(* Logix 5000 project; controller DNP3Outstation 1756-L62 rev 19.11; software revision 19.01 *)

TASK MainTask (continuous, watchdog 500 ms) : DNP3Outstation

MODULES
   Local : 1756-L62 (ICP 0, rev 19.11)
      eth : vendor 1 type 12 code 200 (Ethernet 192.168.1.129, ICP 1, rev 5.7)
         DNPS01 : ETHERNET-MODULE (Ethernet 192.168.1.161, rev 1.1, Output RPI 10 ms)
END_MODULES

TYPE PLX51DNPInput :
STRUCT
   Instance : STRING;
   Status : PLX51DNPStatus;
   MasterMappedStatus : BOOL[1024];
   TransactionRate : DINT;
   Temperature : REAL;
   DNP3RxPacketCount : DINT;
   DNP3TxPacketCount : DINT;
   DNP3ChecksumErrors : DINT;
   DNP3MsgTimeout : DINT;
   AuthenticationFailures : DINT;
   SessionKeyChanges : DINT;
   TagReads : DINT;
   TagWrites : DINT;
   TagConnectionFailures : DINT;
   TagErrors : DINT;
   MasterEventBufferIndex : DINT;
END_STRUCT
END_TYPE

TYPE PLX51DNPOutput :
STRUCT
   RoutingInhibited : BOOL;
END_STRUCT
END_TYPE

TYPE PLX51DNPStatus :
STRUCT
   OutstationMode : BOOL;
   MasterMode : BOOL;
   UnscheduledMode : BOOL;
   ConfigurationValid : BOOL;
   RoutingInhibited : BOOL;
   DNP3EventLogOk : BOOL;
   DNP3EventLogOverflow : BOOL;
END_STRUCT
END_TYPE

TYPE PSDNP3AnalogInput16Flag :
STRUCT
   Online : BOOL;
   Restart : BOOL;
   CommLost : BOOL;
   RemoteForced : BOOL;
   LocalForced : BOOL;
   OverRange : BOOL;
   ReferenceError : BOOL;
   EventTrigger : BOOL;
   Value : INT;
END_STRUCT
END_TYPE

TYPE PSDNP3AnalogInput32Flag :
STRUCT
   Online : BOOL;
   Restart : BOOL;
   CommLost : BOOL;
   RemoteForced : BOOL;
   LocalForced : BOOL;
   OverRange : BOOL;
   ReferenceError : BOOL;
   EventTrigger : BOOL;
   Value : DINT;
END_STRUCT
END_TYPE

TYPE PSDNP3AnalogInputRealFlag :
STRUCT
   Online : BOOL;
   Restart : BOOL;
   CommLost : BOOL;
   RemoteForced : BOOL;
   LocalForced : BOOL;
   OverRange : BOOL;
   ReferenceError : BOOL;
   EventTrigger : BOOL;
   Value : REAL;
END_STRUCT
END_TYPE

TYPE PSDNP3AnalogOutput16 :
STRUCT
   RequestPending : BOOL;
   Reserved : INT;
   Value : INT;
   Status : SINT;
END_STRUCT
END_TYPE

TYPE PSDNP3AnalogOutput32 :
STRUCT
   RequestPending : BOOL;
   Reserved : INT;
   Value : DINT;
   Status : SINT;
END_STRUCT
END_TYPE

TYPE PSDNP3AnalogOutputReal :
STRUCT
   RequestPending : BOOL;
   Reserved : INT;
   Value : REAL;
   Status : SINT;
END_STRUCT
END_TYPE

TYPE PSDNP3AnalogOutputStatus16Flag :
STRUCT
   Online : BOOL;
   Restart : BOOL;
   CommLost : BOOL;
   RemoteForced : BOOL;
   LocalForced : BOOL;
   OverRange : BOOL;
   ReferenceError : BOOL;
   EventTrigger : BOOL;
   Value : INT;
END_STRUCT
END_TYPE

TYPE PSDNP3AnalogOutputStatus32Flag :
STRUCT
   Online : BOOL;
   Restart : BOOL;
   CommLost : BOOL;
   RemoteForced : BOOL;
   LocalForced : BOOL;
   OverRange : BOOL;
   ReferenceError : BOOL;
   EventTrigger : BOOL;
   Value : DINT;
END_STRUCT
END_TYPE

TYPE PSDNP3AnalogOutputStatusRealFlag :
STRUCT
   Online : BOOL;
   Restart : BOOL;
   CommLost : BOOL;
   RemoteForced : BOOL;
   LocalForced : BOOL;
   OverRange : BOOL;
   ReferenceError : BOOL;
   EventTrigger : BOOL;
   Value : REAL;
END_STRUCT
END_TYPE

TYPE PSDNP3BinaryInputPacked :
STRUCT
   BinaryValues : SINT[32];
END_STRUCT
END_TYPE

TYPE PSDNP3BinaryInputWithFlag :
STRUCT
   Online : BOOL;
   Restart : BOOL;
   CommLost : BOOL;
   RemoteForced : BOOL;
   LocalForced : BOOL;
   ChatterFilter : BOOL;
   Reserved : BOOL;
   State : BOOL;
END_STRUCT
END_TYPE

TYPE PSDNP3BinaryOutputPacked :
STRUCT
   BinaryValues : SINT[32];
END_STRUCT
END_TYPE

TYPE PSDNP3BinaryOutputPulse :
STRUCT
   Count : SINT;
   OnTimer : TIMER;
   OffTimer : TIMER;
END_STRUCT
END_TYPE

TYPE PSDNP3BinaryOutputWithFlag :
STRUCT
   Online : BOOL;
   Restart : BOOL;
   CommLost : BOOL;
   RemoteForced : BOOL;
   LocalForced : BOOL;
   Reserved1 : BOOL;
   Reserved2 : BOOL;
   State : BOOL;
END_STRUCT
END_TYPE

TYPE PSDNP3Counter16WithFlag :
STRUCT
   Online : BOOL;
   Restart : BOOL;
   CommLost : BOOL;
   RemoteForced : BOOL;
   LocalForced : BOOL;
   RollOver : BOOL;
   Discontinuity : BOOL;
   EventTrigger : BOOL;
   Value : INT;
END_STRUCT
END_TYPE

TYPE PSDNP3Counter32WithFlag :
STRUCT
   Online : BOOL;
   Restart : BOOL;
   CommLost : BOOL;
   RemoteForced : BOOL;
   LocalForced : BOOL;
   RollOver : BOOL;
   Discontinuity : BOOL;
   EventTrigger : BOOL;
   Value : DINT;
END_STRUCT
END_TYPE

TYPE PSDNP3CounterCtrl :
STRUCT
   FreezeCounter : BOOL;
   ClearCounter : BOOL;
   TimeOfOccurrence : LINT;
END_STRUCT
END_TYPE

TYPE PSDNP3CROB :
STRUCT
   RequestPending : BOOL;
   Reserved : INT;
   ControlCode : SINT;
   Count : SINT;
   OnTime : DINT;
   OffTime : DINT;
   StatusCode : SINT;
END_STRUCT
END_TYPE

TYPE PSDNP3DoubleBinaryInputPacked :
STRUCT
   BinaryValues : SINT[32];
END_STRUCT
END_TYPE

TYPE PSDNP3DoubleBinaryInputWithFlag :
STRUCT
   Online : BOOL;
   Restart : BOOL;
   CommLost : BOOL;
   RemoteForced : BOOL;
   LocalForced : BOOL;
   ChatterFilter : BOOL;
   State0 : BOOL;
   State1 : BOOL;
END_STRUCT
END_TYPE

TYPE PSDNP3FrozenCounter16WithFlag :
STRUCT
   Online : BOOL;
   Restart : BOOL;
   CommLost : BOOL;
   RemoteForced : BOOL;
   LocalForced : BOOL;
   RollOver : BOOL;
   Discontinuity : BOOL;
   EventTrigger : BOOL;
   Value : INT;
END_STRUCT
END_TYPE

TYPE PSDNP3FrozenCounter16WithFlagTimeRev2 :
STRUCT
   Online : BOOL;
   Restart : BOOL;
   CommLost : BOOL;
   RemoteForced : BOOL;
   LocalForced : BOOL;
   RollOver : BOOL;
   Discontinuity : BOOL;
   EventTrigger : BOOL;
   Value : INT;
   Reserved : DINT;
   TimeOfOccurrence : LINT;
END_STRUCT
END_TYPE

TYPE PSDNP3FrozenCounter32WithFlag :
STRUCT
   Online : BOOL;
   Restart : BOOL;
   CommLost : BOOL;
   RemoteForced : BOOL;
   LocalForced : BOOL;
   RollOver : BOOL;
   Discontinuity : BOOL;
   EventTrigger : BOOL;
   Value : DINT;
END_STRUCT
END_TYPE

TYPE PSDNP3FrozenCounter32WithFlagTime :
STRUCT
   Online : BOOL;
   Restart : BOOL;
   CommLost : BOOL;
   RemoteForced : BOOL;
   LocalForced : BOOL;
   RollOver : BOOL;
   Discontinuity : BOOL;
   EventTrigger : BOOL;
   Value : DINT;
   TimeOfOccurrence : LINT;
END_STRUCT
END_TYPE

TYPE PSDNP3LocalKeyUpdateRequest :
STRUCT
   KeyLength : SINT;
   KeyData : SINT[32];
END_STRUCT
END_TYPE

TYPE PSDNP3MasterEvent :
STRUCT
   EvtPending : DINT;
   EvtGroup : SINT;
   EvtFlags : SINT;
   EvtSrcNodeAddress : INT;
   EvtSrcIPAddress : INT[4];
   EvtElementIndex : DINT;
   Reserved : DINT;
   EvtTimeStamp : LINT;
   EvtFloatValue : REAL;
   EvtIntegerValue : DINT;
END_STRUCT
END_TYPE

TYPE PSDNP3RemoteKeyUpdateRequest :
STRUCT
   Command : SINT;
   Option : SINT;
   DestinationNode : INT;
   IPAddress : INT[4];
   KeyData : SINT[255];
END_STRUCT
END_TYPE

ADD_ON_INSTRUCTION PSDNP3AnalogInputEvtLog16   (* revision 1.0, vendor ProSoft Technology Inc *)
VAR_IN_OUT
   DNP3Object : PSDNP3AnalogInput16Flag; {required}
END_VAR
VAR_INPUT
   Deadband : INT; {required}
   MinimumLogInterval : REAL; {required}
   ExtrernalEventTrigger : BOOL; {visible}
END_VAR
VAR_OUTPUT
   EventTriggers : DINT; {access Read Only, visible}
END_VAR
VAR
   RequestLog : BOOL; {access None}
   ExternalONS : BOOL; {access None}
   Interval : TIMER := (PRE := 1000000); {access None}
   PreviousValue : INT; {access None}
   DBRequest : BOOL; {access None}
   ExtRequest : BOOL; {access None}
   Pending : BOOL; {access None}
END_VAR

ROUTINE Logic   (* ladder *)
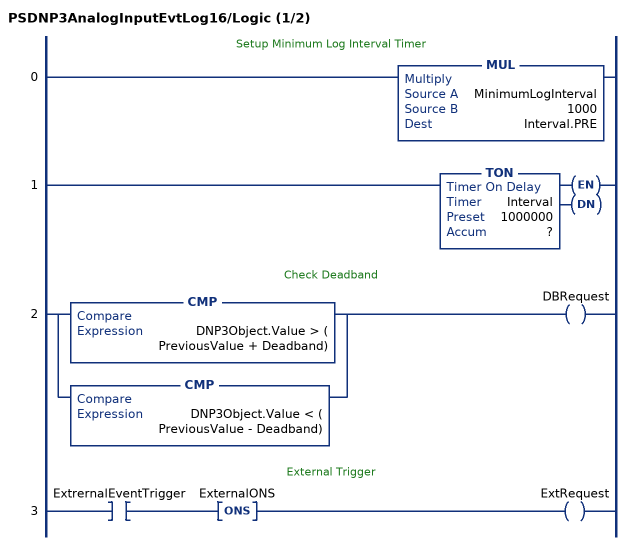
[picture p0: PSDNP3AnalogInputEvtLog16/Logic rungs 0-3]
   // Setup Minimum Log Interval Timer
   0: MUL(MinimumLogInterval,1000,Interval.PRE);
   1: TON(Interval,?,?);
   // Check Deadband
   2: [CMP(DNP3Object.Value > ( PreviousValue + Deadband)) ,CMP(DNP3Object.Value < ( PreviousValue - Deadband)) ]OTE(DBRequest);
   // External Trigger
   3: XIC(ExtrernalEventTrigger)ONS(ExternalONS)OTE(ExtRequest);
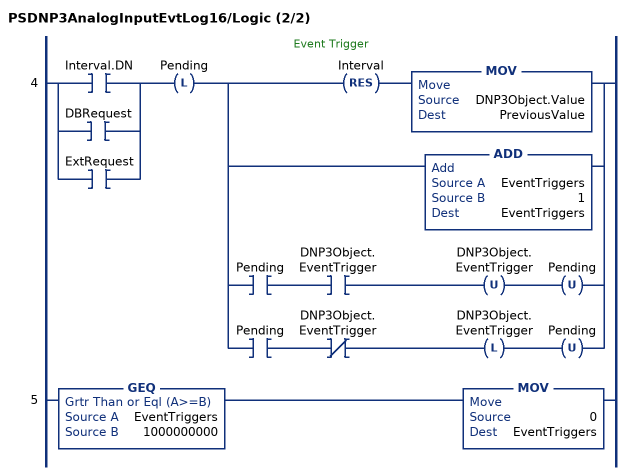
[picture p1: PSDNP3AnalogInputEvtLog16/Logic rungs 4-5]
   // Event Trigger
   4: [XIC(Interval.DN) ,XIC(DBRequest) ,XIC(ExtRequest) ]OTL(Pending)[RES(Interval) MOV(DNP3Object.Value,PreviousValue) ,ADD(EventTriggers,1,EventTriggers) ,XIC(Pending) XIC(DNP3Object.EventTrigger) OTU(DNP3Object.EventTrigger) OTU(Pending) ,XIC(Pending) XIO(DNP3Object.EventTrigger) OTL(DNP3Object.EventTrigger) OTU(Pending) ];
   5: GEQ(EventTriggers,1000000000)MOV(0,EventTriggers);
END_ROUTINE
END_ADD_ON_INSTRUCTION

ADD_ON_INSTRUCTION PSDNP3AnalogInputEvtLog32   (* revision 1.0, vendor ProSoft Technology Inc *)
VAR_IN_OUT
   DNP3Object : PSDNP3AnalogInput32Flag; {required}
END_VAR
VAR_INPUT
   Deadband : DINT; {required}
   MinimumLogInterval : REAL; {required}
   ExtrernalEventTrigger : BOOL; {visible}
END_VAR
VAR_OUTPUT
   EventTriggers : DINT; {access Read Only, visible}
END_VAR
VAR
   RequestLog : BOOL; {access None}
   ExternalONS : BOOL; {access None}
   Interval : TIMER := (PRE := 1000000); {access None}
   PreviousValue : DINT; {access None}
   DBRequest : BOOL; {access None}
   ExtRequest : BOOL; {access None}
   Pending : BOOL; {access None}
END_VAR

ROUTINE Logic   (* ladder *)
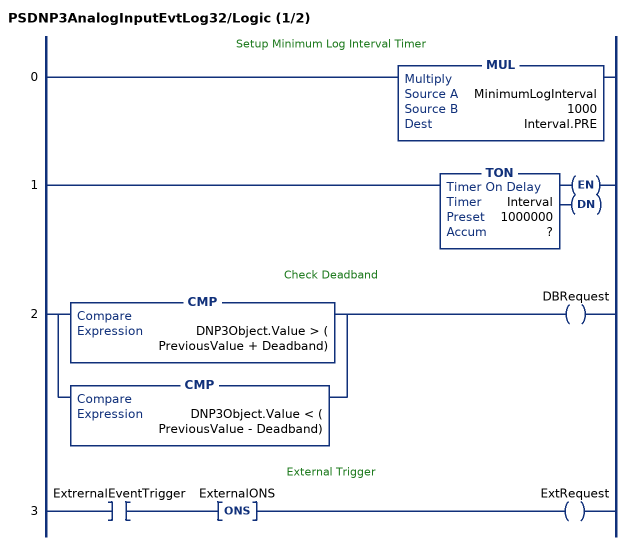
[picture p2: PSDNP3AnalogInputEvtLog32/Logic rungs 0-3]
   // Setup Minimum Log Interval Timer
   0: MUL(MinimumLogInterval,1000,Interval.PRE);
   1: TON(Interval,?,?);
   // Check Deadband
   2: [CMP(DNP3Object.Value > ( PreviousValue + Deadband)) ,CMP(DNP3Object.Value < ( PreviousValue - Deadband)) ]OTE(DBRequest);
   // External Trigger
   3: XIC(ExtrernalEventTrigger)ONS(ExternalONS)OTE(ExtRequest);
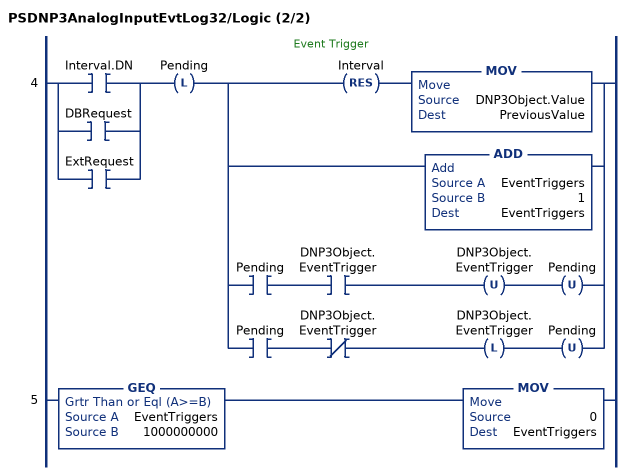
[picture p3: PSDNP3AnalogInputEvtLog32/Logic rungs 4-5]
   // Event Trigger
   4: [XIC(Interval.DN) ,XIC(DBRequest) ,XIC(ExtRequest) ]OTL(Pending)[RES(Interval) MOV(DNP3Object.Value,PreviousValue) ,ADD(EventTriggers,1,EventTriggers) ,XIC(Pending) XIC(DNP3Object.EventTrigger) OTU(DNP3Object.EventTrigger) OTU(Pending) ,XIC(Pending) XIO(DNP3Object.EventTrigger) OTL(DNP3Object.EventTrigger) OTU(Pending) ];
   5: GEQ(EventTriggers,1000000000)MOV(0,EventTriggers);
END_ROUTINE
END_ADD_ON_INSTRUCTION

ADD_ON_INSTRUCTION PSDNP3AnalogInputEvtLogReal   (* revision 1.0, vendor ProSoft Technology Inc *)
VAR_IN_OUT
   DNP3Object : PSDNP3AnalogInputRealFlag; {required}
END_VAR
VAR_INPUT
   Deadband : REAL; {required}
   MinimumLogInterval : REAL; {required}
   ExtrernalEventTrigger : BOOL; {visible}
END_VAR
VAR_OUTPUT
   EventTriggers : DINT; {access Read Only, visible}
END_VAR
VAR
   RequestLog : BOOL; {access None}
   ExternalONS : BOOL; {access None}
   Interval : TIMER := (PRE := 1000000); {access None}
   PreviousValue : REAL; {access None}
   DBRequest : BOOL; {access None}
   ExtRequest : BOOL; {access None}
   Pending : BOOL; {access None}
END_VAR

ROUTINE Logic   (* ladder *)
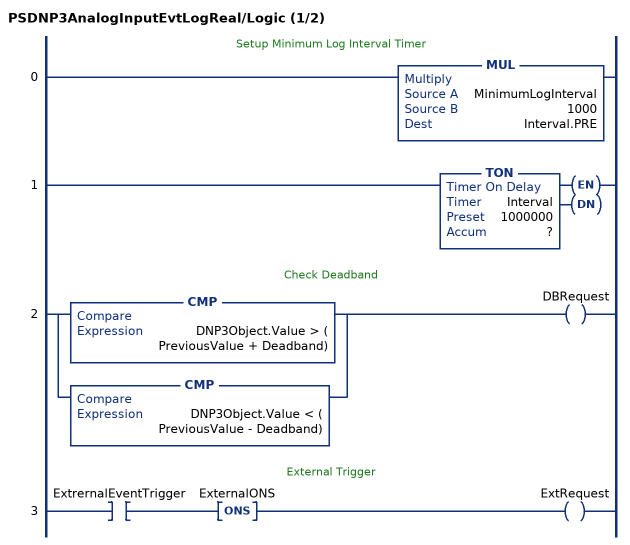
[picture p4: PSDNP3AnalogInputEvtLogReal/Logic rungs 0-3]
   // Setup Minimum Log Interval Timer
   0: MUL(MinimumLogInterval,1000,Interval.PRE);
   1: TON(Interval,?,?);
   // Check Deadband
   2: [CMP(DNP3Object.Value > ( PreviousValue + Deadband)) ,CMP(DNP3Object.Value < ( PreviousValue - Deadband)) ]OTE(DBRequest);
   // External Trigger
   3: XIC(ExtrernalEventTrigger)ONS(ExternalONS)OTE(ExtRequest);
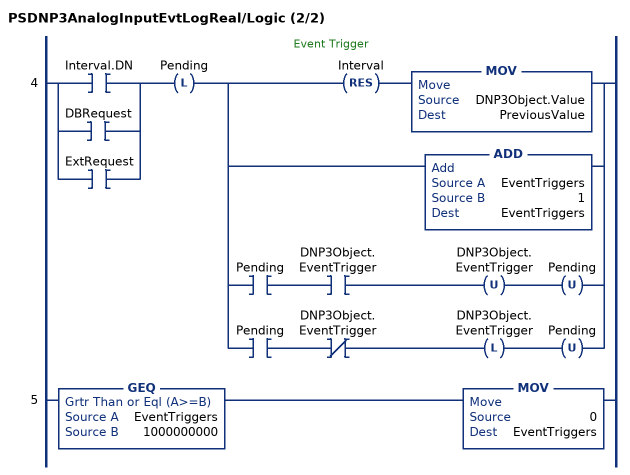
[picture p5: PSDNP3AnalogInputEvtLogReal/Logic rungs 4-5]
   // Event Trigger
   4: [XIC(Interval.DN) ,XIC(DBRequest) ,XIC(ExtRequest) ]OTL(Pending)[RES(Interval) MOV(DNP3Object.Value,PreviousValue) ,ADD(EventTriggers,1,EventTriggers) ,XIC(Pending) XIC(DNP3Object.EventTrigger) OTU(DNP3Object.EventTrigger) OTU(Pending) ,XIC(Pending) XIO(DNP3Object.EventTrigger) OTL(DNP3Object.EventTrigger) OTU(Pending) ];
   5: GEQ(EventTriggers,1000000000)MOV(0,EventTriggers);
END_ROUTINE
END_ADD_ON_INSTRUCTION

ADD_ON_INSTRUCTION PSDNP3AnalogOutput16Control   (* revision 1.0, vendor ProSoft Technology Inc *)
// DNP3 Outstation - Analog Output Control 16
VAR_IN_OUT
   AnalogOutputCommand : PSDNP3AnalogOutput16; {required}
   AnalogOutputStatus : PSDNP3AnalogOutputStatus16Flag; {required}
END_VAR
VAR_OUTPUT
   CurrentOutput : INT; {access Read Only, visible}
   RequestCount : DINT; {access Read Only, visible}
END_VAR
VAR_INPUT
   ResetStatistics : BOOL; {required}
END_VAR
VAR
   RequestCounter : COUNTER := (PRE := 2100000000); {access None}
END_VAR

ROUTINE Logic   (* ladder *)
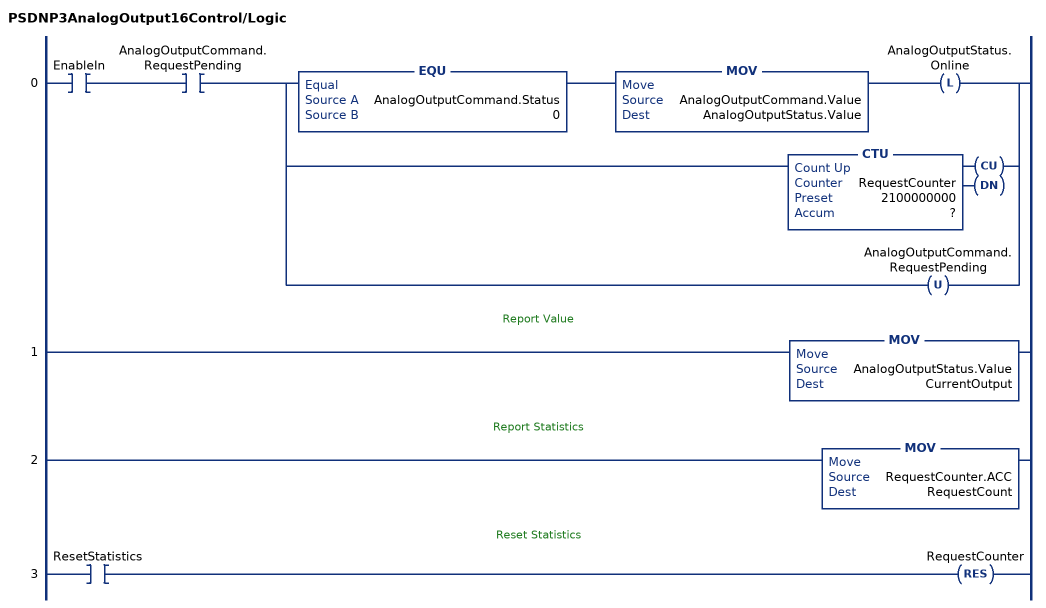
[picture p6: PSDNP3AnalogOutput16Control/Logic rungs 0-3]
   0: XIC(EnableIn)XIC(AnalogOutputCommand.RequestPending)[EQU(AnalogOutputCommand.Status,0) MOV(AnalogOutputCommand.Value,AnalogOutputStatus.Value) OTL(AnalogOutputStatus.Online) ,CTU(RequestCounter,?,?) ,OTU(AnalogOutputCommand.RequestPending) ];
   // Report Value
   1: MOV(AnalogOutputStatus.Value,CurrentOutput);
   // Report Statistics
   2: MOV(RequestCounter.ACC,RequestCount);
   // Reset Statistics
   3: XIC(ResetStatistics)RES(RequestCounter);
END_ROUTINE
END_ADD_ON_INSTRUCTION

ADD_ON_INSTRUCTION PSDNP3AnalogOutput32Control   (* revision 1.0, vendor ProSoft Technology Inc *)
// DNP3 Outstation - Analog Output Control REAL
VAR_IN_OUT
   AnalogOutputCommand : PSDNP3AnalogOutput32; {required}
   AnalogOutputStatus : PSDNP3AnalogOutputStatus32Flag; {required}
END_VAR
VAR_OUTPUT
   CurrentOutput : DINT; {access Read Only, visible}
   RequestCount : DINT; {access Read Only, visible}
END_VAR
VAR_INPUT
   ResetStatistics : BOOL; {required}
END_VAR
VAR
   RequestCounter : COUNTER := (PRE := 2100000000); {access None}
END_VAR

ROUTINE Logic   (* ladder *)
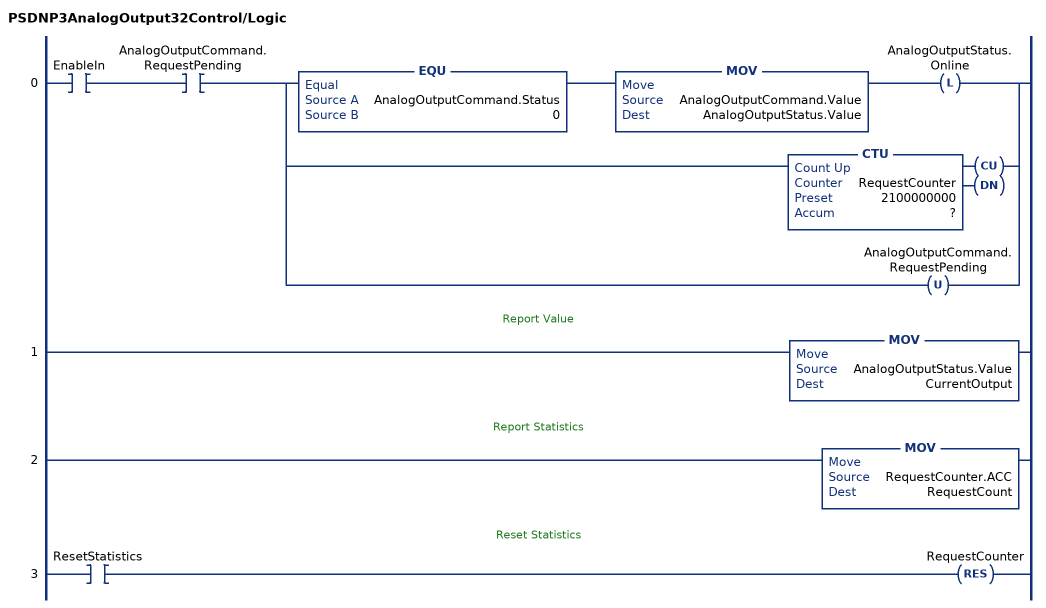
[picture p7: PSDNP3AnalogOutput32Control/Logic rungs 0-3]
   0: XIC(EnableIn)XIC(AnalogOutputCommand.RequestPending)[EQU(AnalogOutputCommand.Status,0) MOV(AnalogOutputCommand.Value,AnalogOutputStatus.Value) OTL(AnalogOutputStatus.Online) ,CTU(RequestCounter,?,?) ,OTU(AnalogOutputCommand.RequestPending) ];
   // Report Value
   1: MOV(AnalogOutputStatus.Value,CurrentOutput);
   // Report Statistics
   2: MOV(RequestCounter.ACC,RequestCount);
   // Reset Statistics
   3: XIC(ResetStatistics)RES(RequestCounter);
END_ROUTINE
END_ADD_ON_INSTRUCTION

ADD_ON_INSTRUCTION PSDNP3AnalogOutputRealControl   (* revision 1.0, vendor ProSoft Technology Inc *)
// DNP3 Outstation - Analog Output Control REAL
VAR_IN_OUT
   AnalogOutputCommand : PSDNP3AnalogOutputReal; {required}
   AnalogOutputStatus : PSDNP3AnalogOutputStatusRealFlag; {required}
END_VAR
VAR_OUTPUT
   CurrentOutput : REAL; {access Read Only, visible}
   RequestCount : DINT; {access Read Only, visible}
END_VAR
VAR_INPUT
   ResetStatistics : BOOL; {required}
END_VAR
VAR
   RequestCounter : COUNTER := (PRE := 2100000000); {access None}
END_VAR

ROUTINE Logic   (* ladder *)
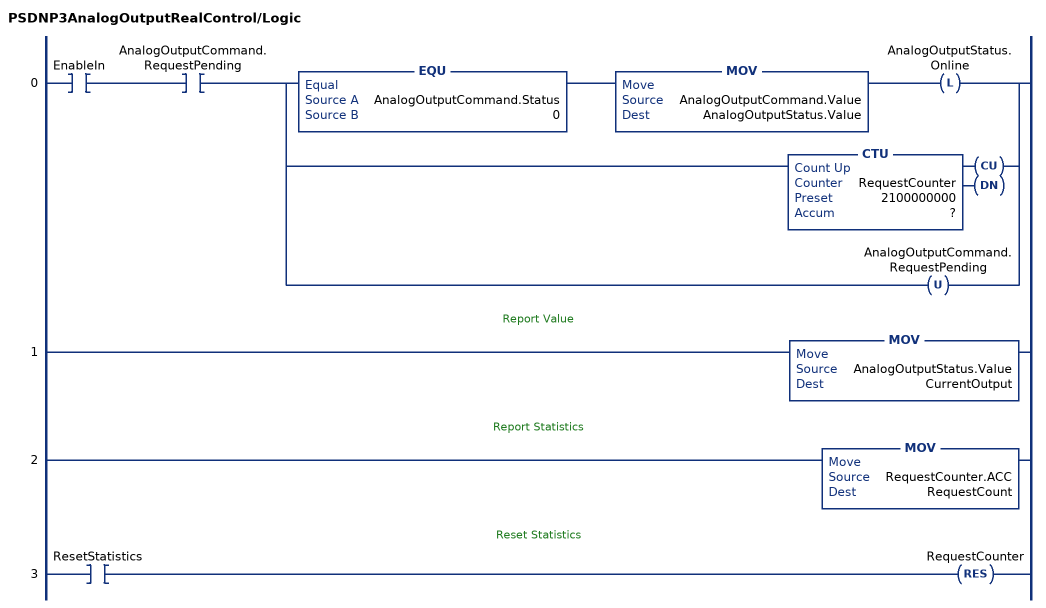
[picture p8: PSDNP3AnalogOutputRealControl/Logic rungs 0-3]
   0: XIC(EnableIn)XIC(AnalogOutputCommand.RequestPending)[EQU(AnalogOutputCommand.Status,0) MOV(AnalogOutputCommand.Value,AnalogOutputStatus.Value) OTL(AnalogOutputStatus.Online) ,CTU(RequestCounter,?,?) ,OTU(AnalogOutputCommand.RequestPending) ];
   // Report Value
   1: MOV(AnalogOutputStatus.Value,CurrentOutput);
   // Report Statistics
   2: MOV(RequestCounter.ACC,RequestCount);
   // Reset Statistics
   3: XIC(ResetStatistics)RES(RequestCounter);
END_ROUTINE
END_ADD_ON_INSTRUCTION

ADD_ON_INSTRUCTION PSDNP3AnalogOutputStatusEvtLog16   (* revision 1.0, vendor ProSoft Technology Inc *)
VAR_IN_OUT
   DNP3Object : PSDNP3AnalogOutputStatus32Flag; {required}
END_VAR
VAR_INPUT
   Deadband : INT; {required}
   MinimumLogInterval : REAL; {required}
   ExtrernalEventTrigger : BOOL; {visible}
END_VAR
VAR_OUTPUT
   EventTriggers : DINT; {access Read Only, visible}
END_VAR
VAR
   RequestLog : BOOL; {access None}
   ExternalONS : BOOL; {access None}
   Interval : TIMER := (PRE := 1000000); {access None}
   PreviousValue : INT; {access None}
   DBRequest : BOOL; {access None}
   ExtRequest : BOOL; {access None}
   Pending : BOOL; {access None}
END_VAR

ROUTINE Logic   (* ladder *)
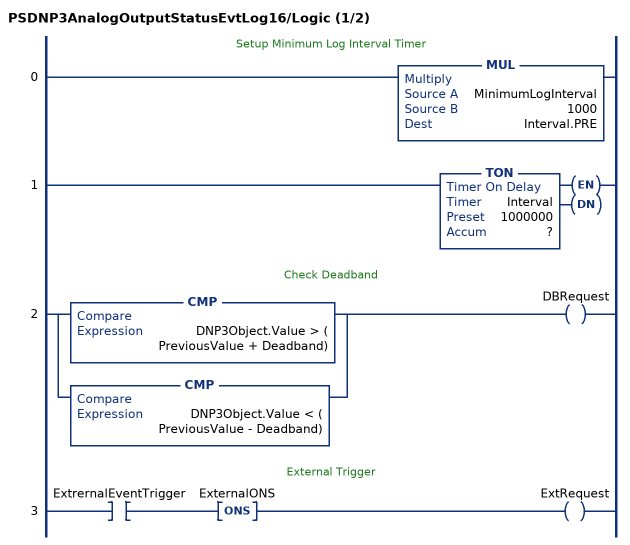
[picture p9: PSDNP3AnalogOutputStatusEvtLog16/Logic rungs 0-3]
   // Setup Minimum Log Interval Timer
   0: MUL(MinimumLogInterval,1000,Interval.PRE);
   1: TON(Interval,?,?);
   // Check Deadband
   2: [CMP(DNP3Object.Value > ( PreviousValue + Deadband)) ,CMP(DNP3Object.Value < ( PreviousValue - Deadband)) ]OTE(DBRequest);
   // External Trigger
   3: XIC(ExtrernalEventTrigger)ONS(ExternalONS)OTE(ExtRequest);
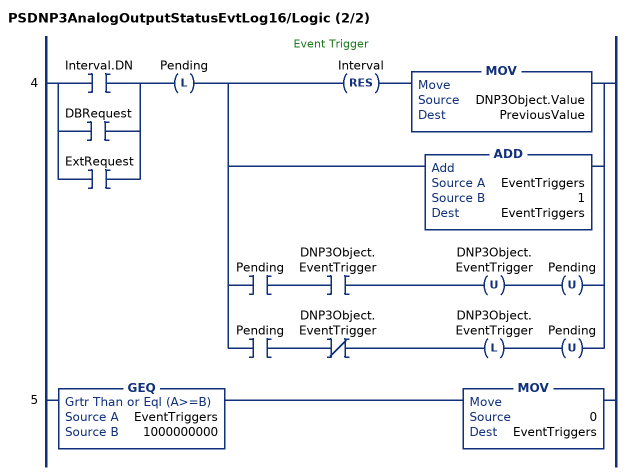
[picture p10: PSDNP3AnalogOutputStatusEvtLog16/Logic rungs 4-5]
   // Event Trigger
   4: [XIC(Interval.DN) ,XIC(DBRequest) ,XIC(ExtRequest) ]OTL(Pending)[RES(Interval) MOV(DNP3Object.Value,PreviousValue) ,ADD(EventTriggers,1,EventTriggers) ,XIC(Pending) XIC(DNP3Object.EventTrigger) OTU(DNP3Object.EventTrigger) OTU(Pending) ,XIC(Pending) XIO(DNP3Object.EventTrigger) OTL(DNP3Object.EventTrigger) OTU(Pending) ];
   5: GEQ(EventTriggers,1000000000)MOV(0,EventTriggers);
END_ROUTINE
END_ADD_ON_INSTRUCTION

ADD_ON_INSTRUCTION PSDNP3AnalogOutputStatusEvtLog32   (* revision 1.0, vendor ProSoft Technology Inc *)
VAR_IN_OUT
   DNP3Object : PSDNP3AnalogOutputStatus32Flag; {required}
END_VAR
VAR_INPUT
   Deadband : DINT; {required}
   MinimumLogInterval : REAL; {required}
   ExtrernalEventTrigger : BOOL; {visible}
END_VAR
VAR_OUTPUT
   EventTriggers : DINT; {access Read Only, visible}
END_VAR
VAR
   RequestLog : BOOL; {access None}
   ExternalONS : BOOL; {access None}
   Interval : TIMER := (PRE := 1000000); {access None}
   PreviousValue : DINT; {access None}
   DBRequest : BOOL; {access None}
   ExtRequest : BOOL; {access None}
   Pending : BOOL; {access None}
END_VAR

ROUTINE Logic   (* ladder *)
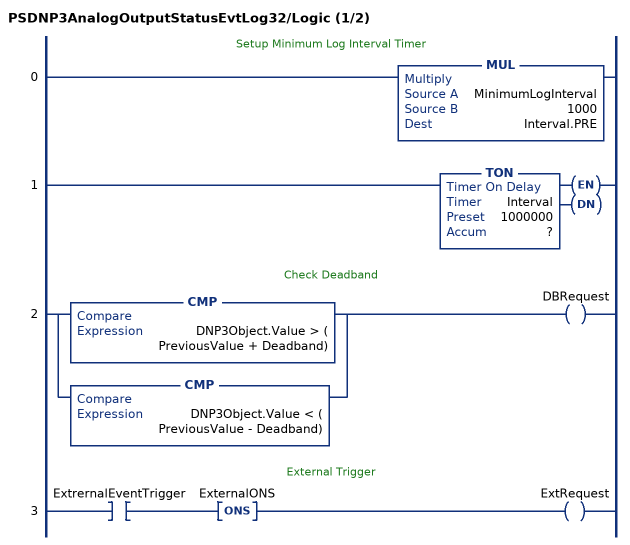
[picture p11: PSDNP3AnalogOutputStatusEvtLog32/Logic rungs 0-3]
   // Setup Minimum Log Interval Timer
   0: MUL(MinimumLogInterval,1000,Interval.PRE);
   1: TON(Interval,?,?);
   // Check Deadband
   2: [CMP(DNP3Object.Value > ( PreviousValue + Deadband)) ,CMP(DNP3Object.Value < ( PreviousValue - Deadband)) ]OTE(DBRequest);
   // External Trigger
   3: XIC(ExtrernalEventTrigger)ONS(ExternalONS)OTE(ExtRequest);
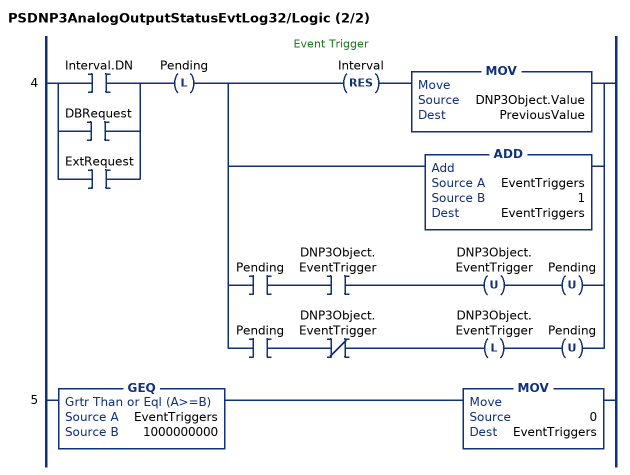
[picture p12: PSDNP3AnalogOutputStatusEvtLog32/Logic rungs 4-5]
   // Event Trigger
   4: [XIC(Interval.DN) ,XIC(DBRequest) ,XIC(ExtRequest) ]OTL(Pending)[RES(Interval) MOV(DNP3Object.Value,PreviousValue) ,ADD(EventTriggers,1,EventTriggers) ,XIC(Pending) XIC(DNP3Object.EventTrigger) OTU(DNP3Object.EventTrigger) OTU(Pending) ,XIC(Pending) XIO(DNP3Object.EventTrigger) OTL(DNP3Object.EventTrigger) OTU(Pending) ];
   5: GEQ(EventTriggers,1000000000)MOV(0,EventTriggers);
END_ROUTINE
END_ADD_ON_INSTRUCTION

ADD_ON_INSTRUCTION PSDNP3AnalogOutputStatusEvtLogReal   (* revision 1.0, vendor ProSoft Technology Inc *)
VAR_IN_OUT
   DNP3Object : PSDNP3AnalogOutputStatusRealFlag; {required}
END_VAR
VAR_INPUT
   Deadband : REAL; {required}
   MinimumLogInterval : REAL; {required}
   ExtrernalEventTrigger : BOOL; {visible}
END_VAR
VAR_OUTPUT
   EventTriggers : DINT; {access Read Only, visible}
END_VAR
VAR
   RequestLog : BOOL; {access None}
   ExternalONS : BOOL; {access None}
   Interval : TIMER := (PRE := 1000000); {access None}
   PreviousValue : REAL; {access None}
   DBRequest : BOOL; {access None}
   ExtRequest : BOOL; {access None}
   Pending : BOOL; {access None}
END_VAR

ROUTINE Logic   (* ladder *)
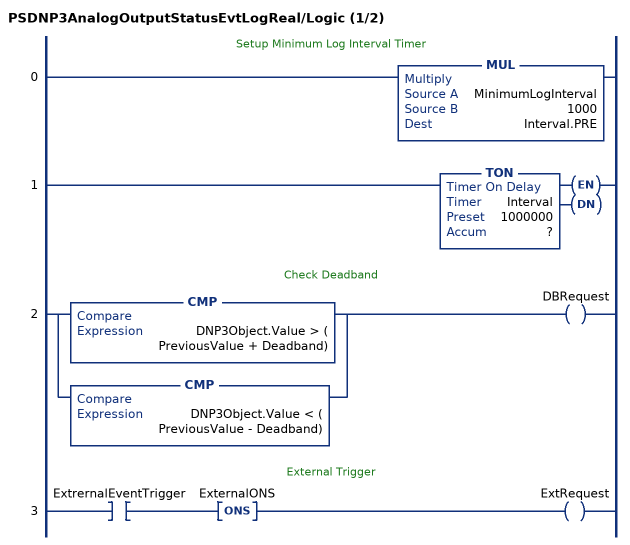
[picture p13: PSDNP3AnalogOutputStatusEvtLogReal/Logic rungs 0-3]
   // Setup Minimum Log Interval Timer
   0: MUL(MinimumLogInterval,1000,Interval.PRE);
   1: TON(Interval,?,?);
   // Check Deadband
   2: [CMP(DNP3Object.Value > ( PreviousValue + Deadband)) ,CMP(DNP3Object.Value < ( PreviousValue - Deadband)) ]OTE(DBRequest);
   // External Trigger
   3: XIC(ExtrernalEventTrigger)ONS(ExternalONS)OTE(ExtRequest);
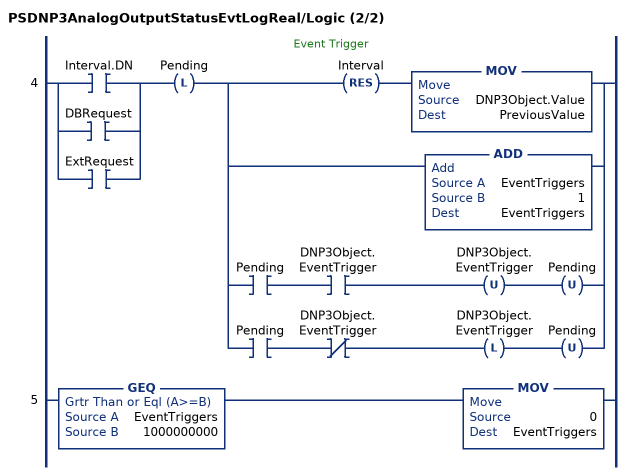
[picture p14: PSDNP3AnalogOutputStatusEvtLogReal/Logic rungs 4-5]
   // Event Trigger
   4: [XIC(Interval.DN) ,XIC(DBRequest) ,XIC(ExtRequest) ]OTL(Pending)[RES(Interval) MOV(DNP3Object.Value,PreviousValue) ,ADD(EventTriggers,1,EventTriggers) ,XIC(Pending) XIC(DNP3Object.EventTrigger) OTU(DNP3Object.EventTrigger) OTU(Pending) ,XIC(Pending) XIO(DNP3Object.EventTrigger) OTL(DNP3Object.EventTrigger) OTU(Pending) ];
   5: GEQ(EventTriggers,1000000000)MOV(0,EventTriggers);
END_ROUTINE
END_ADD_ON_INSTRUCTION

ADD_ON_INSTRUCTION PSDNP3BinaryOutputCROBWithFlag   (* revision 1.0, vendor ProSoft Technology Inc *)
VAR_IN_OUT
   Control : PSDNP3CROB; {required}
   BinaryOutput : PSDNP3BinaryOutputWithFlag; {required}
END_VAR
VAR_OUTPUT
   CurrentState : BOOL; {access Read Only, visible}
   LatchOnRequestCount : DINT; {access Read Only, visible}
   LatchOffRequestCount : DINT; {access Read Only, visible}
   PulseOnRequestCount : DINT; {access Read Only, visible}
   PulseOffRequestCount : DINT; {access Read Only, visible}
   CurrentPulseCount : DINT; {access Read Only, visible}
   CurrentPulseTarget : DINT; {access Read Only, visible}
END_VAR
VAR_INPUT
   ResetStatistics : BOOL; {required}
END_VAR
VAR
   PulseCounter : COUNTER := (PRE := 100); {access None}
   PulseTimer1 : TIMER := (PRE := 1000); {access None}
   PulseTimer2 : TIMER := (PRE := 1000); {access None}
   PulseOn : BOOL; {access None}
   PulseOff : BOOL; {access None}
   PulseOffRequestCounter : COUNTER := (PRE := 2100000000); {access None}
   PulseOnRequestCounter : COUNTER := (PRE := 2100000000); {access None}
   LatchOffRequestCounter : COUNTER := (PRE := 2100000000); {access None}
   LatchOnRequestCounter : COUNTER := (PRE := 2100000000); {access None}
END_VAR

ROUTINE Logic   (* ladder *)
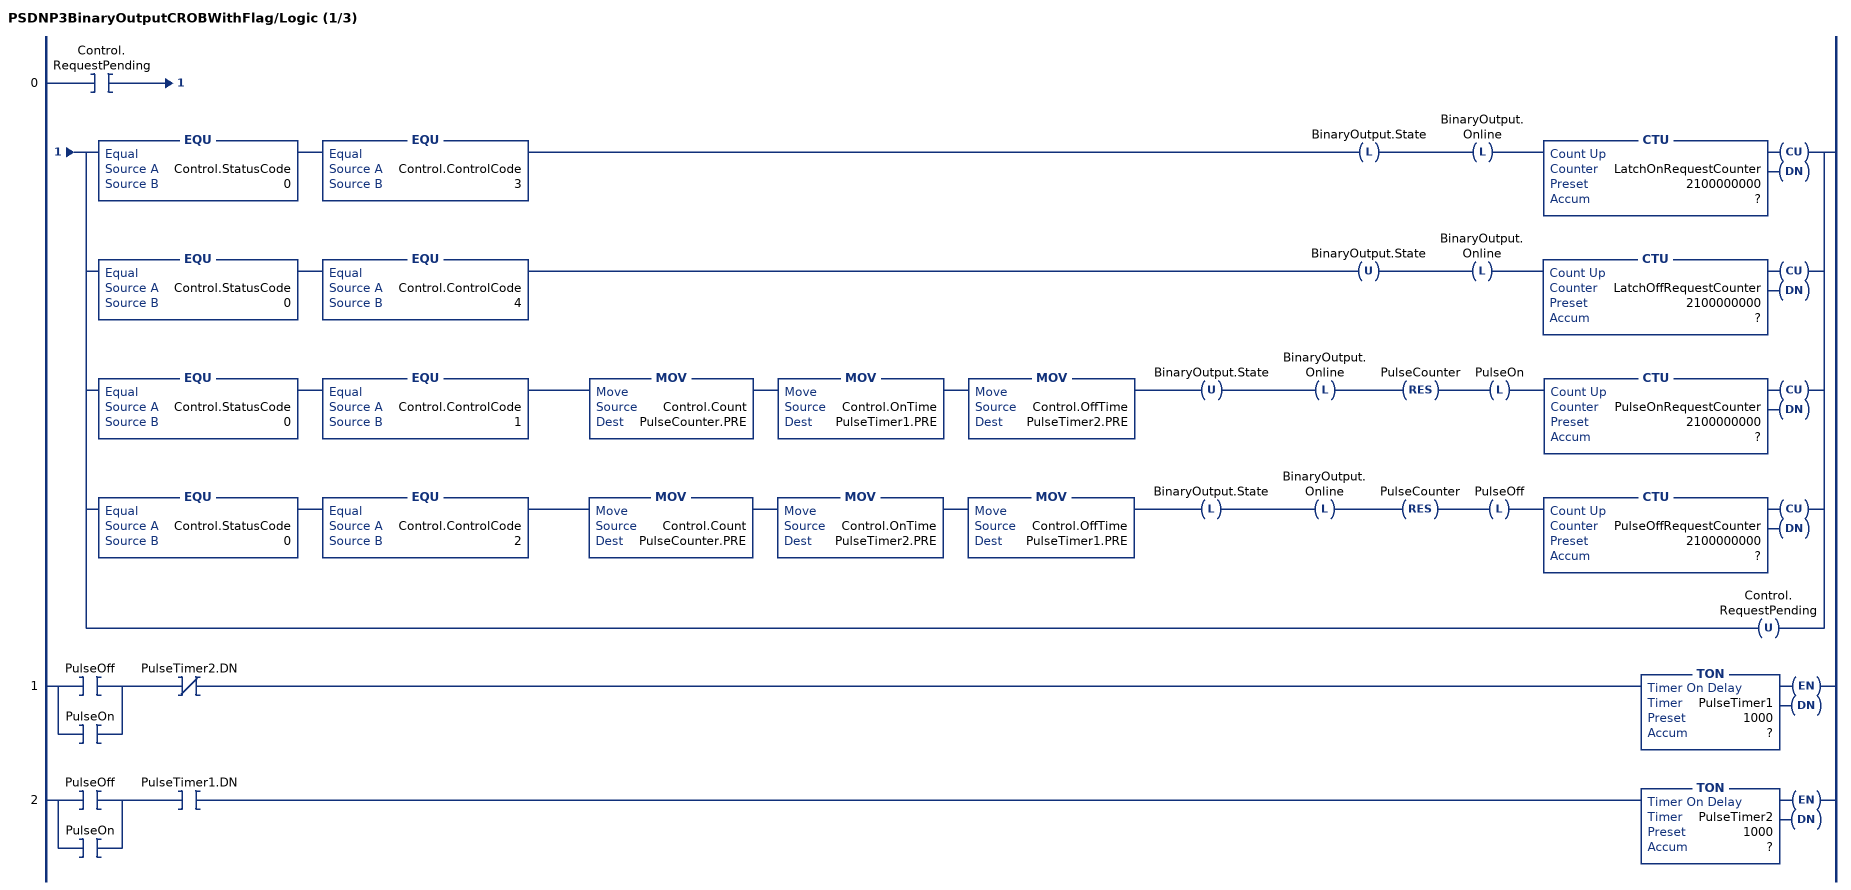
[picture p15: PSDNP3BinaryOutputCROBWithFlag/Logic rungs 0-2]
   0: XIC(Control.RequestPending)[EQU(Control.StatusCode,0) EQU(Control.ControlCode,3) OTL(BinaryOutput.State) OTL(BinaryOutput.Online) CTU(LatchOnRequestCounter,?,?) ,EQU(Control.StatusCode,0) EQU(Control.ControlCode,4) OTU(BinaryOutput.State) OTL(BinaryOutput.Online) CTU(LatchOffRequestCounter,?,?) ,EQU(Control.StatusCode,0) EQU(Control.ControlCode,1) MOV(Control.Count,PulseCounter.PRE) MOV(Control.OnTime,PulseTimer1.PRE) MOV(Control.OffTime,PulseTimer2.PRE) OTU(BinaryOutput.State) OTL(BinaryOutput.Online) RES(PulseCounter) OTL(PulseOn) CTU(PulseOnRequestCounter,?,?) ,EQU(Control.StatusCode,0) EQU(Control.ControlCode,2) MOV(Control.Count,PulseCounter.PRE) MOV(Control.OnTime,PulseTimer2.PRE) MOV(Control.OffTime,PulseTimer1.PRE) OTL(BinaryOutput.State) OTL(BinaryOutput.Online) RES(PulseCounter) OTL(PulseOff) CTU(PulseOffRequestCounter,?,?) ,OTU(Control.RequestPending) ];
   1: [XIC(PulseOff) ,XIC(PulseOn) ]XIO(PulseTimer2.DN)TON(PulseTimer1,?,?);
   2: [XIC(PulseOff) ,XIC(PulseOn) ]XIC(PulseTimer1.DN)TON(PulseTimer2,?,?);
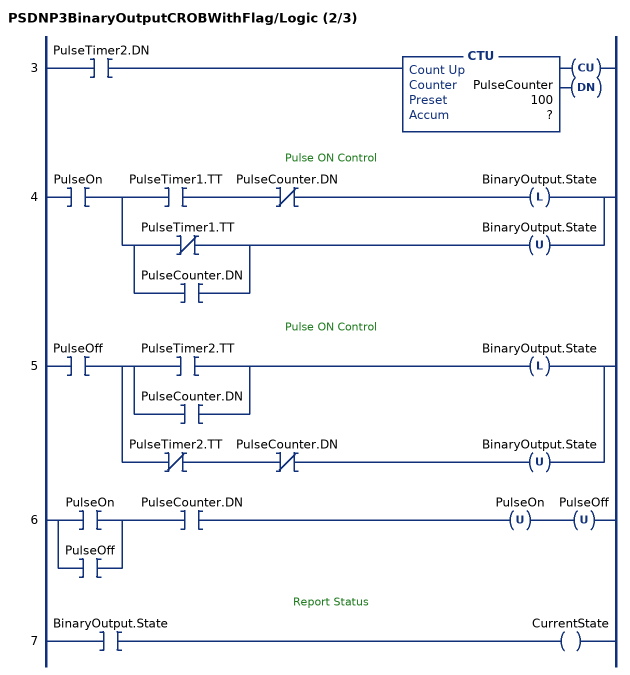
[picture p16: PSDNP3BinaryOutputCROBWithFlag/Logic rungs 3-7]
   3: XIC(PulseTimer2.DN)CTU(PulseCounter,?,?);
   // Pulse ON Control
   4: XIC(PulseOn)[XIC(PulseTimer1.TT) XIO(PulseCounter.DN) OTL(BinaryOutput.State) ,[XIO(PulseTimer1.TT) ,XIC(PulseCounter.DN) ] OTU(BinaryOutput.State) ];
   // Pulse ON Control
   5: XIC(PulseOff)[[XIC(PulseTimer2.TT) ,XIC(PulseCounter.DN) ] OTL(BinaryOutput.State) ,XIO(PulseTimer2.TT) XIO(PulseCounter.DN) OTU(BinaryOutput.State) ];
   6: [XIC(PulseOn) ,XIC(PulseOff) ]XIC(PulseCounter.DN)OTU(PulseOn)OTU(PulseOff);
   // Report Status
   7: XIC(BinaryOutput.State)OTE(CurrentState);
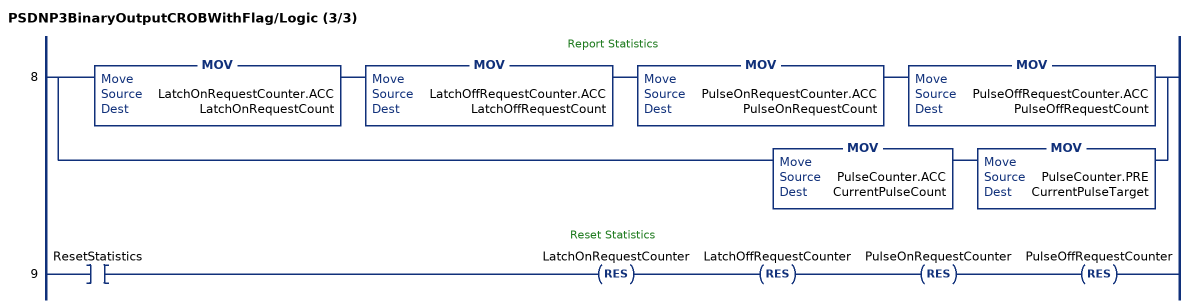
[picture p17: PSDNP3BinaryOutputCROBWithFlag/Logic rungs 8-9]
   // Report Statistics
   8: [MOV(LatchOnRequestCounter.ACC,LatchOnRequestCount) MOV(LatchOffRequestCounter.ACC,LatchOffRequestCount) MOV(PulseOnRequestCounter.ACC,PulseOnRequestCount) MOV(PulseOffRequestCounter.ACC,PulseOffRequestCount) ,MOV(PulseCounter.ACC,CurrentPulseCount) MOV(PulseCounter.PRE,CurrentPulseTarget) ];
   // Reset Statistics
   9: XIC(ResetStatistics)RES(LatchOnRequestCounter)RES(LatchOffRequestCounter)RES(PulseOnRequestCounter)RES(PulseOffRequestCounter);
END_ROUTINE
END_ADD_ON_INSTRUCTION
